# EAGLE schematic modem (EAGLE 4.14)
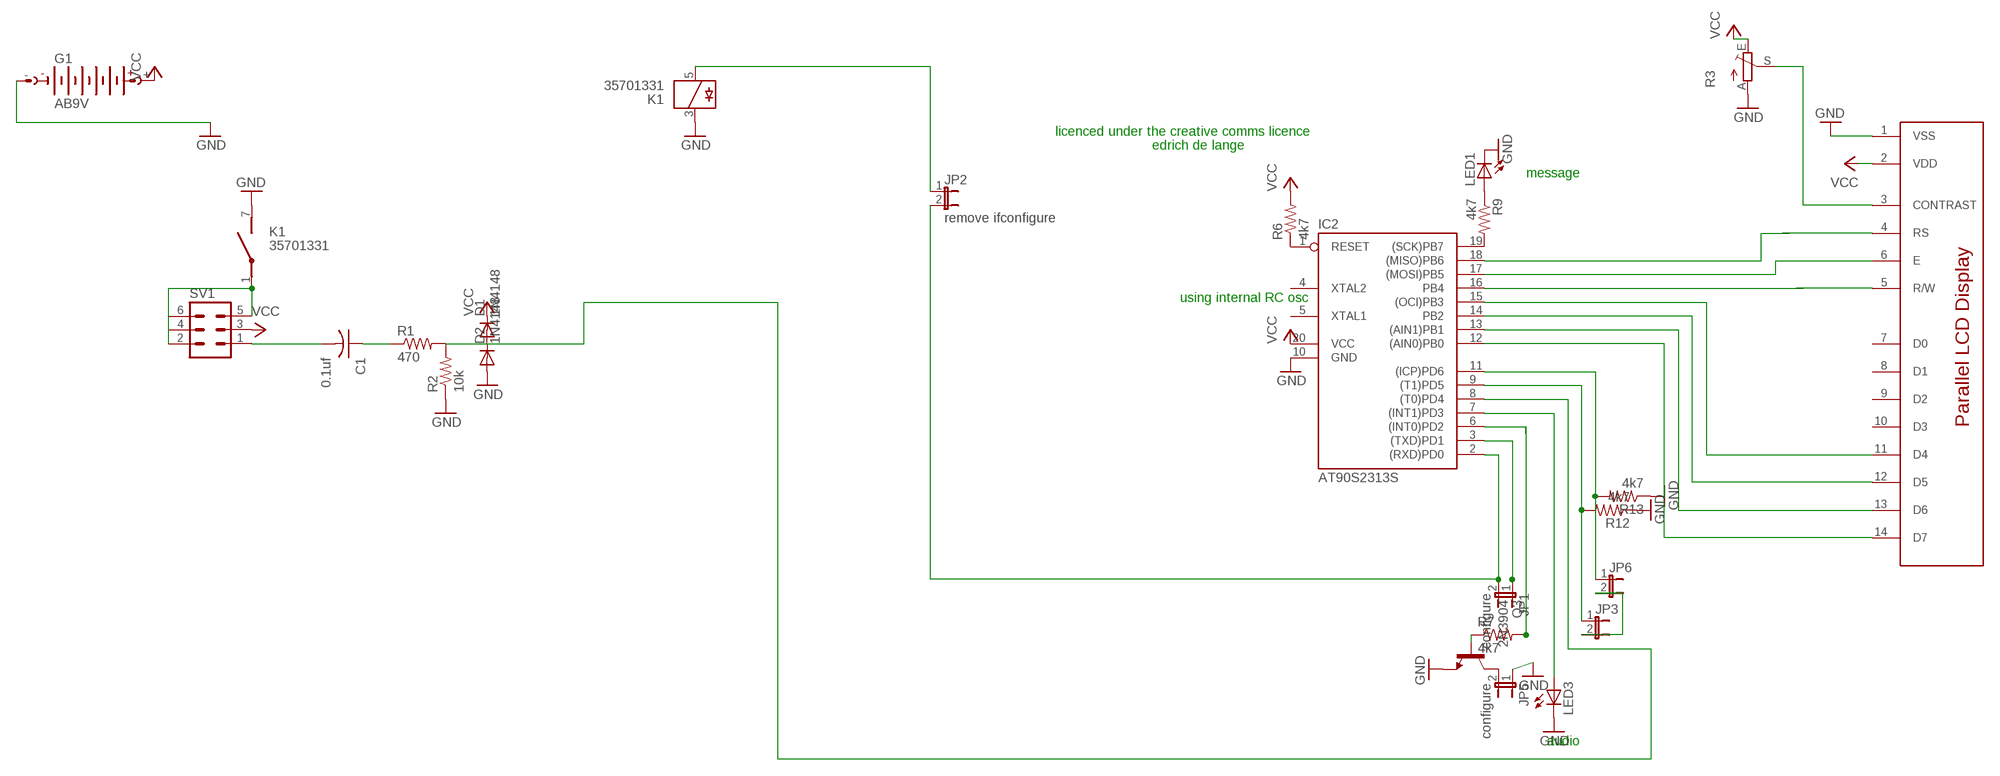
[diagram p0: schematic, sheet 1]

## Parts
C1  0.1uf  CAP-2,5  [C-2,5]
D1  1N4148  [DO35-10]
D2  1N4148  [DO35-10]
G1  AB9V  [AB9V]
IC2  AT90S2313S  [SO20L]
JP1  configure  JP1E  [JP1]
JP2  remove ifconfigure  JP1E  [JP1]
JP3  JP1E  [JP1]
JP5  configure  JP1E  [JP1]
JP6  JP1E  [JP1]
K1  35701331  [REED]
LED1  LEDP-LCC-2-BACK  [P-LCC-2-TOPLED-RG]
LED3  LEDP-LCC-2-BACK  [P-LCC-2-TOPLED-RG]
Q3  2N3904  [TO92]
R1  470  R-US_M3516  [M3516]
R2  10k  R-US_M3516  [M3516]
R3  TRIM_EU-LI15  [LI15]
R6  4k7  R-US_M3516  [M3516]
R7  4k7  R-US_M3516  [M3516]
R9  4k7  R-US_M3516  [M3516]
R12  4k7  R-US_M3516  [M3516]
R13  4k7  R-US_M3516  [M3516]
SV1  MA03-2  [MA03-2]
U$2  PARALLEL_LCDDIP  [DIP_14]

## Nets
GND: D2.A G1.- IC2.10(GND) JP5.1 K1.3 K1.7(2:S) LED1.C LED3.C Q3.3(E) R2.1 R3.A R12.1 R13.1 U$2.1(VSS)
N$1: K1.1(2:P) SV1.2 SV1.4 SV1.5 SV1.6
N$2: JP2.1 K1.5
N$3: C1.2 SV1.1
N$4: C1.1 R1.1
N$5: D1.A D2.C IC2.8((T0)PD4) R1.2 R2.2
N$9: IC2.2((RXD)PD0) JP1.2 JP2.2
N$10: IC2.7((INT1)PD3) LED3.A
N$12: IC2.17((MOSI)PB5) U$2.6(E)
N$13: IC2.16(PB4) U$2.5(R/W)
N$14: IC2.9((T1)PD5) JP3.1 R12.2
N$15: R3.S U$2.3(CONTRAST)
N$16: IC2.15((OCI)PB3) U$2.11(D4)
N$17: IC2.14(PB2) U$2.12(D5)
N$18: IC2.13((AIN1)PB1) U$2.13(D6)
N$19: IC2.12((AIN0)PB0) U$2.14(D7)
N$20: IC2.3((TXD)PD1) JP1.1
N$21: IC2.6((INT0)PD2) R7.2
N$22: IC2.19((SCK)PB7) R9.2
N$23: LED1.A R9.1
N$24: IC2.11((ICP)PD6) JP6.1 R13.2
N$25: IC2.18((MISO)PB6) U$2.4(RS)
N$26: IC2.1(RESET) R6.1
N$27: Q3.2(B) R7.1
N$28: JP3.2 JP6.2
N$29: JP5.2 Q3.1(C)
VCC: D1.C G1.+ IC2.20(VCC) R3.E R6.2 SV1.3 U$2.2(VDD)
Unconnected: IC2.4(XTAL2) IC2.5(XTAL1) U$2.7(D0) U$2.8(D1) U$2.9(D2) U$2.10(D3)

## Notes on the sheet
- licenced under the creative comms licence
- edrich de lange
- message
- using internal RC osc
- audio

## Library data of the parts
C1 = discrete:CAP-2,5
D1 D2 = diode:1N4148: DIODE
G1 = battery:AB9V: 9-V BATTERY CLIP
IC2 = avr:AT90S2313: MICROCONTROLLER 2 Kbytes FLASH 128 bytes SRAM 128 bytes EEPROM UART
JP1-JP3 JP5 JP6 = jumper:JP1E: JUMPER
K1 = relay:35701331: RELAY reed, 1 x norm. open with polarity
LED1 LED3 = led:LED: LED
Q3 = transistor-npn:2N3904: NPN Transistor
R1 R2 R6 R7 R9 R12 R13 = rcl:R-US_: RESISTOR, American symbol
R3 = pot:TRIM_EU-: POTENTIOMETER
SV1 = con-lstb:MA03-2: PIN HEADER
U$2 = lcd:PARALLEL_LCD: Parallel LCD Alphanumeric LCD's usually common characters x line are 20x4, 2x16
